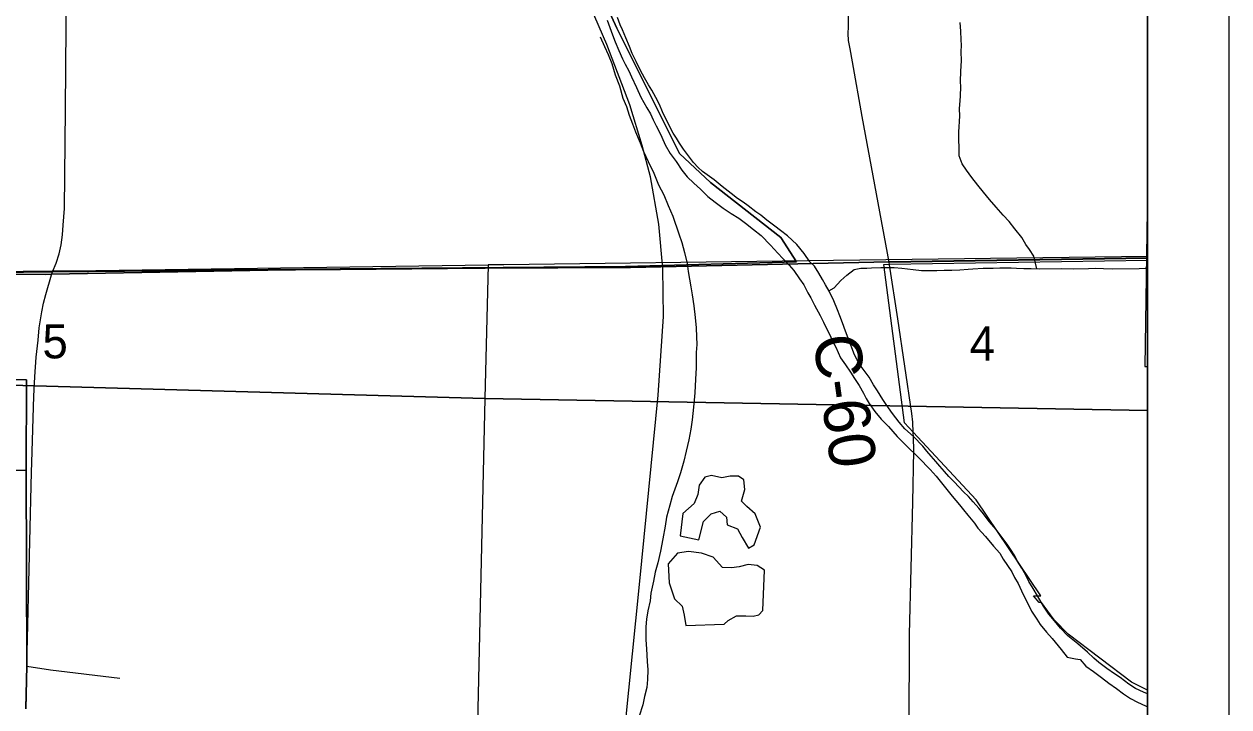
# Model space of a CAD drawing. Extents: x 0 to 34, y -5 to 22.
# Drawn here: x 7.522 to 9, y 16.047 to 16.885 of the extents above; entities that cross this region are included whole.
import ezdxf

# ---------------------------------------------------------------- set-up
doc = ezdxf.new("R2010")
doc.units = 0
for name, color, linetype in [('Default', 7, 'Continuous'), ('GM_X_City_Street', 7, 'Continuous'), ('GM_X_County_Road', 7, 'Continuous'), ('GM_X_County_Road_Text', 7, 'Continuous'), ('GM_X_Major_River', 7, 'Continuous'), ('GM_X_Minor_Lake', 7, 'Continuous'), ('GM_X_Minor_River', 7, 'Continuous'), ('GM_X_Rail_Line', 7, 'Continuous'), ('GM_X_Section', 7, 'Continuous'), ('GM_X_Section_Text', 7, 'Continuous'), ('GM_X_Township_Road', 7, 'Continuous'), ('GM_X_US_Route', 7, 'Continuous'), ('SC_Scratch2', 7, 'Continuous'), ('SH_Cut_Line', 7, 'Continuous'), ('SH_Data', 7, 'Continuous')]:
    doc.layers.add(name, color=color, linetype=linetype)

msp = doc.modelspace()

# ---------------------------------------------------------------- linework, layer by layer
at = {"layer": 'Default'}
msp.add_lwpolyline([(8.9, 16.4647), (8.9, 16.6836), (8.8967, 16.4646)], close=True, dxfattribs=at)
at = {"layer": 'GM_X_City_Street'}
msp.add_lwpolyline([(7.5563, 16.581), (7.5609, 16.5914), (7.5645, 16.603), (7.5671, 16.6139), (7.5685, 16.6262), (7.5695, 16.638), (7.5711, 16.6586), (7.5723, 16.7799), (7.574, 16.984), (7.5756, 17.1841), (7.578, 17.3878)], dxfattribs=at)
for points in [[(8.9, 16.4107), (8.9, 16.5998), (8.4829, 16.5944), (8.1103, 16.5896), (8.0908, 16.5893), (8.0868, 16.4255)], [(8.9, 15.4101), (8.9, 16.4107), (8.0868, 16.4255), (8.0646, 15.4287)]]:
    msp.add_lwpolyline(points, close=True, dxfattribs=at)
at = {"layer": 'GM_X_County_Road'}
msp.add_line((8.5831, 16.5927), (8.9, 16.5975), dxfattribs=at)
for points in [[(8.5831, 16.5927), (8.5501, 16.7715), (8.5381, 16.8384), (8.5352, 16.8545), (8.5333, 16.8647), (8.5328, 16.8734), (8.533, 16.8815), (8.5331, 16.8961), (8.5376, 16.9958)], [(8.6129, 16.3779), (8.6127, 16.3838), (8.612, 16.3965), (8.611, 16.4071), (8.5939, 16.5232), (8.5837, 16.5896), (8.5831, 16.5927)], [(7.0657, 16.5753), (7.1658, 16.5765), (7.5563, 16.581)], [(7.5341, 16.4441), (7.5345, 16.4519), (7.5364, 16.4761), (7.5386, 16.4971), (7.5402, 16.512), (7.5431, 16.5318), (7.5455, 16.5426), (7.5482, 16.5532), (7.5553, 16.5773), (7.5563, 16.581)], [(7.5306, 16.3351), (7.5309, 16.347), (7.5333, 16.4285), (7.5341, 16.4441)], [(8.6066, 15.9447), (8.6069, 15.9615), (8.6077, 16.0182), (8.6081, 16.1361), (8.6122, 16.2981), (8.6134, 16.3612), (8.6129, 16.3779)], [(7.5238, 16.047), (7.5244, 16.0747), (7.525, 16.0968), (7.5286, 16.2498), (7.5306, 16.3351)]]:
    msp.add_lwpolyline(points, dxfattribs=at)
at = {"layer": 'GM_X_Major_River'}
for points in [[(8.2371, 16.8897), (8.2402, 16.8806), (8.2437, 16.8716), (8.2468, 16.8632), (8.2515, 16.8523), (8.2558, 16.8424), (8.2592, 16.8356), (8.2635, 16.8277), (8.267, 16.8201), (8.2732, 16.8069), (8.2782, 16.7952), (8.2856, 16.7823), (8.2902, 16.7748), (8.2933, 16.7676), (8.2972, 16.76), (8.301, 16.7529), (8.3041, 16.746), (8.3084, 16.7366), (8.3142, 16.726), (8.3215, 16.7162), (8.3288, 16.7057), (8.335, 16.6974), (8.3434, 16.6898), (8.3514, 16.6823), (8.3606, 16.6733), (8.3694, 16.6662), (8.3793, 16.6591), (8.3893, 16.6523), (8.3984, 16.6467), (8.4069, 16.6407), (8.4168, 16.6329), (8.426, 16.6254), (8.4375, 16.6137), (8.4463, 16.6039), (8.4524, 16.5971), (8.4605, 16.5892), (8.4662, 16.5825), (8.4732, 16.5723), (8.4785, 16.5651), (8.4832, 16.5553), (8.4871, 16.5489), (8.4913, 16.5398), (8.4983, 16.5273), (8.5025, 16.519), (8.5064, 16.5107), (8.5103, 16.5035)], [(8.544, 16.4727), (8.5405, 16.4791), (8.5327, 16.4996), (8.5296, 16.5079), (8.5257, 16.5185), (8.5226, 16.5268), (8.5198, 16.5344), (8.5152, 16.5454), (8.5094, 16.5571), (8.5051, 16.565), (8.5013, 16.5714), (8.4966, 16.5794), (8.4916, 16.5877), (8.4859, 16.5933), (8.4789, 16.6035), (8.4697, 16.6144), (8.4582, 16.6249), (8.4498, 16.6317), (8.4429, 16.6369), (8.433, 16.6444), (8.4254, 16.6504), (8.4196, 16.6546), (8.4101, 16.6617), (8.4039, 16.6662), (8.3971, 16.671), (8.389, 16.677), (8.3783, 16.6857), (8.3684, 16.6939), (8.3542, 16.704), (8.3485, 16.7089), (8.3431, 16.7149), (8.3355, 16.7247), (8.3305, 16.7315), (8.3258, 16.7387), (8.322, 16.7451), (8.3181, 16.7511), (8.3104, 16.7663), (8.305, 16.7772), (8.3011, 16.7863), (8.2968, 16.795), (8.2918, 16.8037), (8.2876, 16.8105), (8.2829, 16.8188), (8.2779, 16.8278), (8.2725, 16.8388), (8.2678, 16.8486), (8.2643, 16.8573), (8.2601, 16.8679), (8.2558, 16.8778), (8.2531, 16.8838), (8.2496, 16.8929)], [(8.5103, 16.5035), (8.5134, 16.4956), (8.5176, 16.4884), (8.5234, 16.4755), (8.5296, 16.4669), (8.5357, 16.4578), (8.5404, 16.4499), (8.5462, 16.4412), (8.5516, 16.4321), (8.555, 16.4253), (8.5585, 16.4193), (8.5654, 16.4095), (8.5731, 16.4001), (8.5823, 16.391), (8.5931, 16.379), (8.603, 16.3688), (8.6195, 16.3527), (8.6333, 16.3384), (8.6406, 16.3301), (8.6475, 16.3218), (8.654, 16.3139), (8.6602, 16.3056), (8.6694, 16.2951), (8.6744, 16.289), (8.6798, 16.2823), (8.6878, 16.2725), (8.692, 16.2664), (8.7013, 16.2563), (8.7112, 16.2442), (8.7189, 16.2356), (8.7228, 16.2284), (8.7282, 16.2205), (8.7335, 16.2129), (8.7367, 16.2057), (8.7413, 16.1986), (8.7455, 16.1895), (8.7486, 16.1823), (8.7548, 16.1706), (8.7579, 16.1645), (8.7641, 16.1547), (8.7683, 16.1483), (8.776, 16.1389), (8.7833, 16.131), (8.7941, 16.1174), (8.8017, 16.108), (8.8116, 16.1058), (8.8173, 16.1051), (8.8246, 16.0972), (8.8338, 16.0905), (8.8437, 16.083), (8.8525, 16.0762), (8.8621, 16.0695), (8.8705, 16.0631), (8.8793, 16.0575), (8.888, 16.0527), (8.8976, 16.0482), (8.9, 16.0471)], [(8.9, 16.063), (8.8951, 16.0649), (8.8852, 16.0698), (8.8772, 16.075), (8.8665, 16.0829), (8.8596, 16.0877), (8.8504, 16.0941), (8.8405, 16.1016), (8.8344, 16.1068), (8.8263, 16.1143), (8.8145, 16.1245), (8.8022, 16.1342), (8.7934, 16.1436), (8.7861, 16.1527), (8.7792, 16.161), (8.7723, 16.1708), (8.7653, 16.1832), (8.7596, 16.1923), (8.7545, 16.201), (8.7507, 16.2085), (8.7457, 16.2172), (8.7402, 16.2263), (8.7375, 16.2323), (8.7321, 16.2406), (8.7279, 16.2467), (8.7206, 16.2565), (8.7145, 16.2648), (8.706, 16.2746), (8.6987, 16.284), (8.693, 16.2908), (8.686, 16.2987), (8.6803, 16.3051), (8.6745, 16.3111), (8.6627, 16.3231), (8.6565, 16.3299), (8.6511, 16.3359), (8.6454, 16.3423), (8.6404, 16.3483), (8.6347, 16.3547), (8.6293, 16.3608), (8.6243, 16.3668), (8.6128, 16.3788), (8.6024, 16.3882), (8.5955, 16.3965), (8.5871, 16.4071), (8.5794, 16.418), (8.5752, 16.4244), (8.5686, 16.435), (8.564, 16.4422), (8.5586, 16.4516), (8.5486, 16.4648), (8.544, 16.4727)]]:
    msp.add_lwpolyline(points, dxfattribs=at)
at = {"layer": 'GM_X_Minor_Lake'}
for points in [[(8.3496, 16.2521), (8.3551, 16.2746), (8.3645, 16.2838), (8.3751, 16.2874), (8.3835, 16.2798), (8.3844, 16.2704), (8.397, 16.2655), (8.4027, 16.255), (8.4105, 16.2418), (8.4176, 16.246), (8.425, 16.2674), (8.4188, 16.284), (8.4085, 16.293), (8.4019, 16.2994), (8.406, 16.3139), (8.4047, 16.3257), (8.3982, 16.3301), (8.388, 16.33), (8.3777, 16.328), (8.3652, 16.3309), (8.3568, 16.329), (8.3501, 16.319), (8.3483, 16.3076), (8.3439, 16.2965), (8.3299, 16.2842), (8.3268, 16.2568)], [(8.3268, 16.2568), (8.3496, 16.2521)], [(8.4301, 16.2146), (8.4209, 16.2206), (8.4099, 16.2216), (8.3989, 16.2188), (8.3898, 16.2176), (8.3784, 16.2179), (8.3673, 16.2307), (8.3528, 16.2358), (8.3368, 16.2376), (8.3232, 16.2355), (8.3119, 16.2225), (8.3133, 16.1993), (8.3196, 16.1796), (8.3291, 16.1706), (8.3315, 16.1596), (8.3335, 16.1467), (8.3806, 16.1487), (8.3855, 16.153), (8.3957, 16.1588), (8.4071, 16.1589), (8.4162, 16.1582), (8.423, 16.1598), (8.4279, 16.1652)], [(8.4279, 16.1652), (8.4301, 16.2146)]]:
    msp.add_lwpolyline(points, dxfattribs=at)
at = {"layer": 'GM_X_Minor_River'}
for points in [[(8.7641, 16.5846), (8.7605, 16.6), (8.7551, 16.6083), (8.7509, 16.6144), (8.7459, 16.623), (8.7371, 16.6336), (8.7305, 16.6426), (8.7229, 16.6505), (8.7144, 16.6603), (8.7064, 16.6697), (8.6987, 16.6788), (8.6918, 16.6874), (8.6845, 16.6965), (8.6779, 16.7055), (8.6725, 16.7135), (8.669, 16.7233), (8.6687, 16.7529), (8.6691, 16.7586), (8.6694, 16.7659), (8.6697, 16.7719), (8.6696, 16.7811), (8.6703, 16.7906), (8.6706, 16.7967), (8.6709, 16.8077), (8.6708, 16.8145), (8.6711, 16.8271), (8.6714, 16.8331), (8.6717, 16.84), (8.6716, 16.851), (8.6719, 16.859), (8.6715, 16.8654), (8.671, 16.8761), (8.6701, 16.8867)], [(8.2286, 16.8694), (8.2337, 16.8573), (8.2383, 16.8474), (8.2426, 16.8365), (8.2469, 16.8228), (8.252, 16.8092), (8.2563, 16.794), (8.2606, 16.7838), (8.2641, 16.7732), (8.268, 16.7626), (8.2719, 16.7528), (8.2777, 16.7392), (8.2816, 16.7286), (8.2874, 16.7161), (8.2944, 16.7018), (8.3002, 16.6878), (8.3064, 16.6753), (8.3119, 16.6624), (8.3177, 16.6492), (8.3251, 16.6276), (8.3286, 16.617), (8.3318, 16.6045), (8.335, 16.5912), (8.3366, 16.5814), (8.3398, 16.5624), (8.3414, 16.5526), (8.3434, 16.5393), (8.3451, 16.5249), (8.3463, 16.5123), (8.3468, 16.5013), (8.3469, 16.4918), (8.3463, 16.4819), (8.3464, 16.4724), (8.3461, 16.4629), (8.3454, 16.4493), (8.3445, 16.4322), (8.3431, 16.415), (8.3414, 16.3991), (8.3396, 16.3877), (8.3374, 16.3747), (8.3341, 16.361), (8.3312, 16.3484), (8.3272, 16.3343), (8.3235, 16.3233), (8.3168, 16.305), (8.3139, 16.2947), (8.3099, 16.2798), (8.3081, 16.2688), (8.3052, 16.2532), (8.3023, 16.238), (8.2994, 16.2239), (8.2961, 16.2124), (8.2939, 16.2014), (8.2906, 16.1865), (8.2896, 16.177), (8.287, 16.1649), (8.2852, 16.1546), (8.2846, 16.1451), (8.2843, 16.1295), (8.2852, 16.1181), (8.2861, 16.1029), (8.287, 16.0923), (8.2867, 16.0805), (8.2857, 16.071), (8.2827, 16.0596), (8.2806, 16.0497), (8.2761, 16.0356)], [(8.5091, 16.5577), (8.5154, 16.5613), (8.5237, 16.5702), (8.5312, 16.5767), (8.5402, 16.5836), (8.5482, 16.5852), (8.5558, 16.5853), (8.5615, 16.5858), (8.5728, 16.5863), (8.5823, 16.5864), (8.5892, 16.586), (8.5986, 16.5854), (8.6127, 16.5836), (8.6226, 16.5826), (8.6359, 16.5824), (8.6416, 16.5824), (8.6507, 16.5829), (8.6598, 16.583), (8.67, 16.5835), (8.6799, 16.584), (8.6859, 16.5844), (8.6985, 16.5853), (8.7106, 16.5854), (8.7189, 16.5859), (8.7269, 16.5856), (8.7326, 16.5857), (8.7394, 16.5854), (8.7482, 16.5851), (8.7573, 16.5848), (8.7679, 16.5845), (8.7945, 16.5848), (8.8096, 16.5846), (8.8279, 16.5848), (8.8362, 16.5852), (8.8461, 16.585), (8.8571, 16.5847), (8.8897, 16.585), (8.8973, 16.5855), (8.9, 16.5855)]]:
    msp.add_lwpolyline(points, dxfattribs=at)
at = {"layer": 'GM_X_Rail_Line'}
msp.add_lwpolyline([(8.2459, 15.8933), (8.2766, 16.1971), (8.2997, 16.4296), (8.3061, 16.5262), (8.3053, 16.585), (8.3004, 16.6392), (8.2904, 16.6976), (8.2798, 16.736), (8.2647, 16.7856), (8.2365, 16.86), (8.1723, 17.0083), (8.1702, 17.0135), (8.1453, 17.0686), (8.1275, 17.1149), (8.1174, 17.1532), (8.1048, 17.2213), (8.1029, 17.2684), (8.1046, 17.3175), (8.1138, 17.3772), (8.1273, 17.4342), (8.1499, 17.5184), (8.2132, 17.7643)], dxfattribs=at)
at = {"layer": 'GM_X_Section'}
for points in [[(8.0908, 16.5893), (8.0868, 16.4255), (7.0252, 16.4555), (7.0271, 16.5765), (7.0829, 16.5767), (7.553, 16.5816)], [(7.0252, 16.4555), (8.0868, 16.4255), (8.0646, 15.4287), (6.9989, 15.4538)]]:
    msp.add_lwpolyline(points, close=True, dxfattribs=at)
at = {"layer": 'GM_X_Township_Road'}
for points in [[(7.5563, 16.581), (7.6888, 16.5821), (7.9097, 16.5839), (8.2598, 16.5869)], [(7.525, 16.0968), (7.5541, 16.0925), (7.6391, 16.0821)]]:
    msp.add_lwpolyline(points, dxfattribs=at)
at = {"layer": 'GM_X_US_Route'}
for points in [[(5.8013, 16.5622), (5.8852, 16.5633), (6.0263, 16.5646), (6.0369, 16.5647), (6.1314, 16.5662), (6.137, 16.5663), (6.3903, 16.5692), (6.5815, 16.5715), (6.8205, 16.573), (6.884, 16.5737), (7.1656, 16.577), (7.5561, 16.5815), (7.6886, 16.5826), (7.9095, 16.5845), (8.2655, 16.5864), (8.5829, 16.5932), (8.9, 16.5981), (8.9, 20.9), (4.0002, 20.9)], [(8.9, 14.1), (8.9, 16.5981), (8.5829, 16.5932), (8.2655, 16.5864), (7.9095, 16.5845), (7.6886, 16.5826), (7.5561, 16.5815), (7.1656, 16.577)]]:
    msp.add_lwpolyline(points, dxfattribs=at)
at = {"layer": 'SC_Scratch2'}
for points in [[(8.9, 16.0187), (8.9, 16.0675), (8.8803, 16.0775), (8.8026, 16.1361), (8.7855, 16.1539), (8.7699, 16.1753), (8.7671, 16.1753), (8.7601, 16.1833), (8.7694, 16.1833), (8.69, 16.3012), (8.6125, 16.3843), (8.602, 16.3956), (8.5767, 16.59), (8.5835, 16.5901), (8.9, 16.5953), (8.9, 19.8443)], [(8.1991, 16.9894), (8.2488, 16.8797), (8.2937, 16.7898), (8.3258, 16.7262), (8.364, 16.6907), (8.4501, 16.6231), (8.4693, 16.593), (8.2596, 16.5874), (7.9095, 16.5845), (7.5551, 16.5779), (7.5472, 16.5777), (7.3409, 16.5784)], [(7.3409, 16.5784), (7.5472, 16.5777), (7.5551, 16.5779), (7.9095, 16.5845), (8.2596, 16.5874), (8.4693, 16.593), (8.4501, 16.6231), (8.364, 16.6907), (8.3258, 16.7262), (8.2937, 16.7898), (8.2488, 16.8797), (8.1991, 16.9894)], [(7.0515, 16.4566), (7.5245, 16.4482), (7.5242, 16.3371), (7.5248, 16.0973), (7.5235, 16.0445)], [(7.5, 16.3376), (7.5242, 16.3371), (7.5245, 16.4482), (7.0515, 16.4566)], [(7.5235, 16.0445), (7.5248, 16.0973), (7.5242, 16.3371), (7.5, 16.3376)]]:
    msp.add_lwpolyline(points, dxfattribs=at)
at = {"layer": 'SH_Cut_Line'}
msp.add_lwpolyline([(8.9, 14.1), (8.9, 20.9)], dxfattribs=at)
at = {"layer": 'SH_Data'}
for p, q in [((9, 21), (9, 14)), ((8.9, 20.9), (8.9, 14.1))]:
    msp.add_line(p, q, dxfattribs=at)

# ---------------------------------------------------------------- texts
at = {"layer": 'GM_X_County_Road_Text'}
msp.add_text('C-60', height=0.05682, rotation=277.888, dxfattribs=at).set_placement((8.4895, 16.5005))
at = {"layer": 'GM_X_Section_Text'}
for s, p in [('5', (7.544, 16.4747)), ('4', (8.6819, 16.472))]:
    msp.add_text(s, height=0.0419, rotation=0, dxfattribs=at).set_placement(p)

doc.saveas('drawing.dxf')
